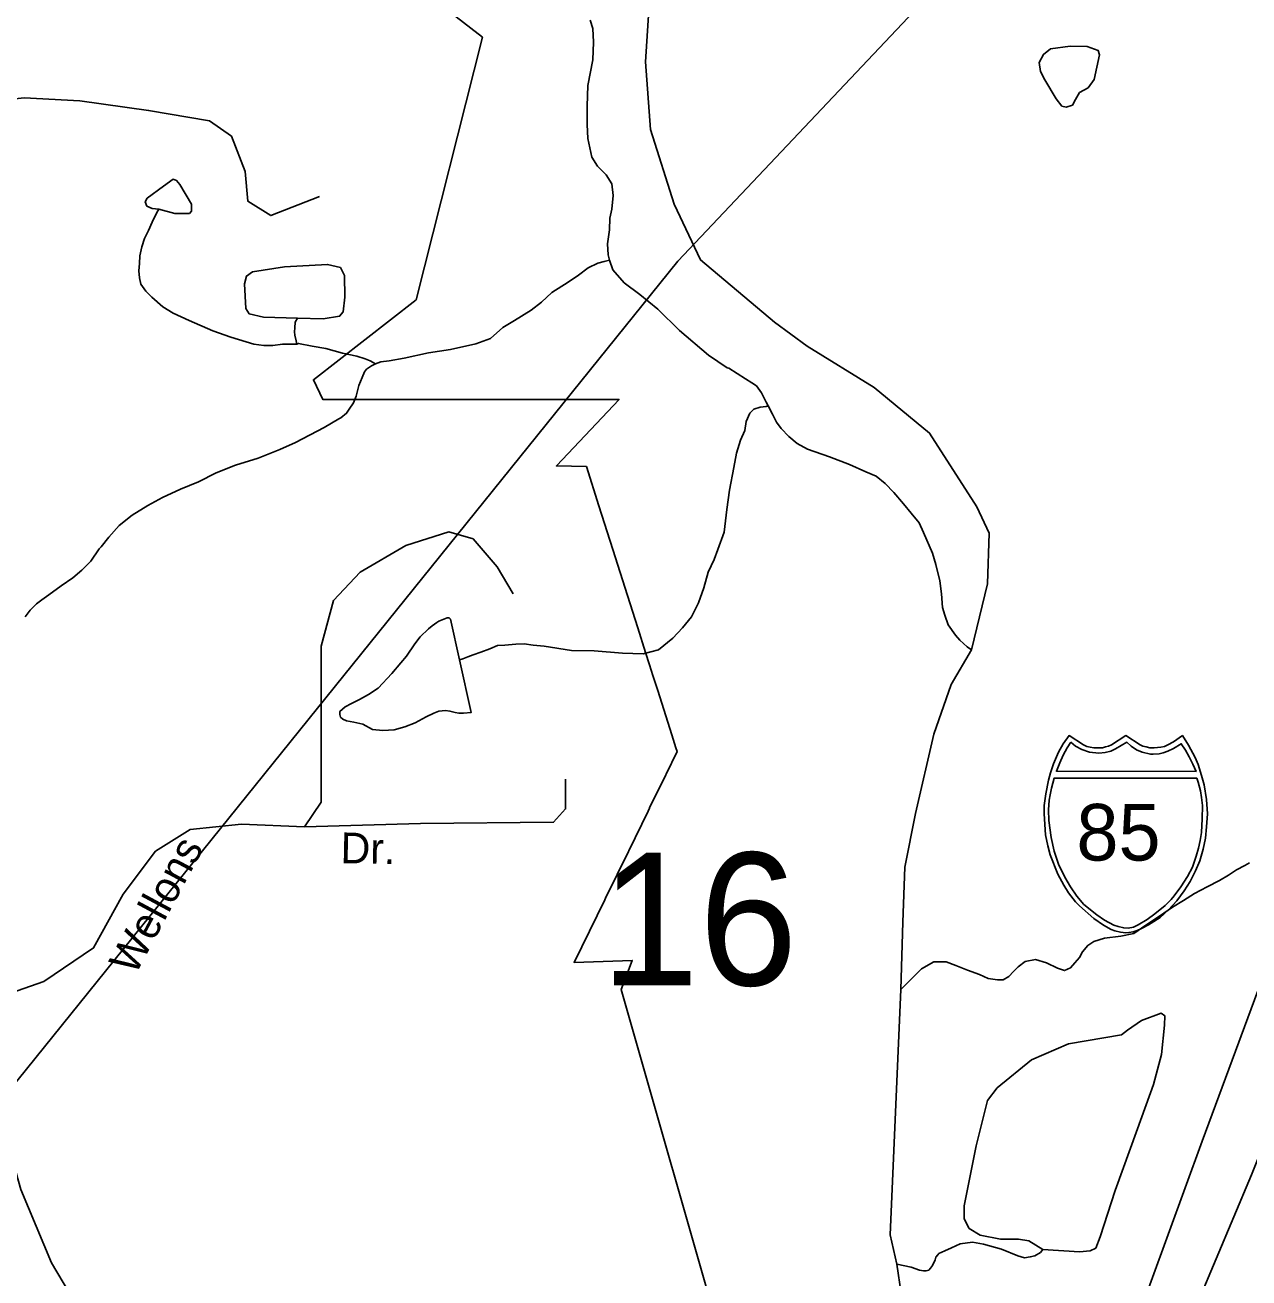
# Model space of a CAD drawing. Extents: x 2056842 to 2160602, y 826753 to 1016856.
# Drawn here: x 2066259 to 2070045, y 850316 to 854191 of the extents above; entities that cross this region are included whole.
import ezdxf

# ---------------------------------------------------------------- set-up
doc = ezdxf.new("R2010")
doc.units = 0
for name, color, linetype in [('Exist Boundary Political City Limit New', 7, 'Continuous'), ('Exist Hydrographic Creek Single Shore', 7, 'Continuous'), ('Exist Hydrographic Misc Water Feature', 7, 'Continuous'), ('Exist Road Non-System Type 51', 7, 'Continuous'), ('Exist Road Non-System Type 51 Label', 7, 'Continuous'), ('Exist Road Primary Interstate Divided Center Attributed', 7, 'Continuous'), ('Exist Road Primary Interstate Shield CELL', 7, 'Continuous'), ('Exist Road Primary Interstate Shield Number Label', 7, 'Continuous'), ('Exist Road Secondary Structure Standard Bridge Number Label', 7, 'Continuous'), ('Exist Road Secondary Type 51 Attributed', 7, 'Continuous'), ('Exist Utilities Gas Line', 7, 'Continuous'), ('Map Preparation Boundary City Limit Buffer Line', 7, 'Continuous')]:
    doc.layers.add(name, color=color, linetype=linetype)

msp = doc.modelspace()

# ---------------------------------------------------------------- linework, layer by layer
at = {"layer": 'Exist Boundary Political City Limit New'}
msp.add_lwpolyline([(2067132, 854572.3), (2067673.5, 854152.8), (2067469, 853340.9), (2067150.9, 853093.5), (2067179.6, 853032.6), (2067340.5, 853032.6), (2067723, 853032.6), (2068096.2, 853032.5), (2067902.6, 852827), (2067995.5, 852824.9), (2068034.2, 852703.3), (2068077.2, 852568.1), (2068122.2, 852426.6), (2068154.1, 852326.4), (2068178.5, 852250.1), (2068190.8, 852211.5), (2068201, 852179.3), (2068215.9, 852132.4), (2068259.5, 851995), (2068272.1, 851955.5), (2068275.9, 851943.8), (2068241.5, 851873.5), (2068240.8, 851871.8), (2068190.9, 851769.8), (2068190, 851768.1), (2068185.9, 851759.6), (2068126, 851636.9), (2068125, 851634.9), (2068054.1, 851489.8), (2068052.2, 851484.6), (2067957.1, 851291.3), (2068137, 851297.5), (2068103, 851207.4), (2068419.8, 850100.1)], dxfattribs=at)
at = {"layer": 'Exist Hydrographic Creek Single Shore'}
for points in [[(2069186.7, 852257.8), (2069236, 852462.5), (2069241.1, 852618.7), (2069202.7, 852700.6), (2069056.9, 852928.5), (2068885.6, 853069.9), (2068678.4, 853197.9), (2068577.3, 853272.1), (2068348.6, 853464.2), (2068266.7, 853637), (2068193.8, 853867.4), (2068178.4, 854076.7), (2068197.6, 854381.3)], [(2068007.3, 854205.4), (2068015.3, 854179.4), (2068017.1, 854137.3), (2068015.3, 854083.2), (2067999.5, 854003.3), (2067997.6, 853939.5), (2067997.8, 853883.4), (2067999.7, 853839.3), (2068011.8, 853781.5), (2068030, 853753.6), (2068055.9, 853727.3), (2068074.1, 853699.4), (2068078, 853663.5), (2068073.9, 853621.5), (2068068, 853593.6), (2068066.3, 853557.7), (2068060.2, 853513.7), (2068062.6, 853479.6), (2068066.3, 853463.6)], [(2067343.1, 853142.4), (2067359.1, 853148.5), (2067385.1, 853152.3), (2067431.1, 853160.3), (2067507.3, 853176.4), (2067574.8, 853186.8), (2067653.1, 853205), (2067698.7, 853220.7), (2067737.2, 853255.1), (2067773.1, 853277.2), (2067824.8, 853309.2), (2067856.8, 853333.1), (2067888.5, 853363.2), (2067938.6, 853395.3), (2067970.8, 853417.3), (2068000.7, 853439.5), (2068030.2, 853453.7), (2068050.3, 853459.6), (2068066.3, 853463.6)], [(2068066.3, 853463.6), (2068076.6, 853433.6), (2068112.5, 853393.8), (2068160.4, 853357.7), (2068216.6, 853311.8), (2068282.9, 853245.8), (2068372.7, 853170), (2068431.1, 853130.4), (2068435.6, 853128.9), (2068487.1, 853096.3), (2068507.2, 853084.3), (2068521.3, 853074.5), (2068537.1, 853052.6), (2068551.3, 853024.5), (2068557.2, 853012.6)], [(2066258.8, 852360.2), (2066275, 852380.5), (2066294.7, 852400.2), (2066310.9, 852412.4), (2066332.6, 852428.6), (2066370.3, 852456.5), (2066406.4, 852480.7), (2066434.5, 852504.8), (2066462.6, 852532.6), (2066488, 852570.9), (2066494.6, 852576.8), (2066518.4, 852606.9), (2066550.2, 852642.7), (2066589.9, 852674.8), (2066638.3, 852704.8), (2066684.1, 852729.1), (2066740.2, 852755.1), (2066795.8, 852777.5), (2066849.7, 852805.4), (2066909.8, 852829.6), (2066979.7, 852851.4), (2067047.4, 852877.6), (2067095.8, 852899.9), (2067183.8, 852945.8), (2067229.3, 852972.2), (2067235.4, 852976.1), (2067253.5, 852990), (2067261.5, 853002.2), (2067275, 853022), (2067283, 853042.3), (2067291.2, 853076), (2067301.3, 853100.1), (2067309.3, 853118.3), (2067315.4, 853126.3), (2067331, 853136.1), (2067343.1, 853142.4)], [(2068557.2, 853012.6), (2068571.2, 852986.6), (2068583.3, 852962.4), (2068597.4, 852942.4), (2068621.4, 852918.5), (2068647.6, 852896.7), (2068679.4, 852878.9), (2068747.3, 852854.8), (2068809.6, 852831.1), (2068859.5, 852808.9), (2068891.7, 852795.2), (2068919.7, 852773), (2068945.8, 852745.2), (2068975.9, 852709.3), (2068999.7, 852681.4), (2069024.1, 852651.3), (2069037.9, 852621.6), (2069066.2, 852557.7), (2069076, 852521.7), (2069088.1, 852471.6), (2069094, 852431.8), (2069096.5, 852389.6), (2069104.3, 852365.7), (2069114.1, 852335.7), (2069136.5, 852303.6), (2069150.4, 852287.7), (2069172.6, 852267.7), (2069186.7, 852257.8)], [(2068968.5, 850267.6), (2068955.1, 850358.8), (2068934.5, 850448.8), (2068967.9, 851207.4), (2068974.5, 851416), (2068980.2, 851585.7), (2069013.4, 851752.1), (2069069.7, 851997.9), (2069123.5, 852151.2), (2069186.7, 852257.8)], [(2070045.9, 851599.2), (2070031.7, 851591.2), (2070005.7, 851577.4), (2069981.7, 851561.5), (2069954, 851545.4), (2069915.9, 851525.2), (2069875.9, 851504.9), (2069842.1, 851482.9), (2069808, 851462.8), (2069767.8, 851434.9), (2069726, 851406.7), (2069688.3, 851380.8), (2069648.1, 851372.7), (2069598.3, 851366.9), (2069564.4, 851356.6), (2069546.2, 851344.3), (2069530.2, 851324.5), (2069520.3, 851306.5), (2069506.6, 851290.3), (2069492.5, 851274.6), (2069474.4, 851266.3), (2069452.5, 851274.1), (2069418.2, 851290.3), (2069384.6, 851300.3), (2069352.4, 851294.2), (2069330.3, 851278.1), (2069316.5, 851263.9), (2069302.4, 851248.2), (2069284.5, 851237.9), (2069266.7, 851237.8), (2069238.4, 851242.1), (2069210.7, 851254), (2069174.2, 851267.6), (2069138.3, 851281.6), (2069108.6, 851293.8), (2069070.3, 851293.6), (2069032.1, 851271.7), (2069014.3, 851253.8), (2068967.9, 851207.4)]]:
    msp.add_lwpolyline(points, dxfattribs=at)
at = {"layer": 'Exist Hydrographic Misc Water Feature'}
for points in [[(2069413.2, 854021.1), (2069448, 853962.8), (2069465.9, 853939.3), (2069479.4, 853937), (2069498.4, 853942.6), (2069508.5, 853960.6), (2069520.9, 853981.9), (2069547.8, 853996.5), (2069565.7, 854022.3), (2069582.5, 854098.5), (2069578, 854112), (2069544.4, 854124.3), (2069491.7, 854125.5), (2069431.2, 854116.5), (2069408.8, 854099.7), (2069395.3, 854075), (2069399.8, 854046.9), (2069413.2, 854021.1)], [(2066672.4, 853621.1), (2066652.3, 853622.9), (2066635.6, 853630.6), (2066630.5, 853643.4), (2066636.9, 853654.9), (2066686.8, 853692), (2066717.5, 853713.8), (2066727.7, 853709.9), (2066738, 853697.1), (2066773.8, 853637), (2066773.8, 853615.2), (2066767.4, 853607.5), (2066722.6, 853607.5), (2066672.4, 853621.1)], [(2066672.4, 853621.1), (2066666, 853611.1), (2066652.5, 853581.1), (2066640.6, 853554.9), (2066628.5, 853530.8), (2066620.3, 853504.8), (2066614.3, 853476.9), (2066612.9, 853452.8), (2066610.5, 853430.8), (2066612.9, 853409), (2066616.6, 853388.9), (2066632.6, 853367), (2066650.8, 853348.9), (2066684.9, 853318.9), (2066716.9, 853299.1), (2066766.9, 853277.3), (2066839.3, 853245.2), (2066895.1, 853225.4), (2066967, 853203.5), (2066997, 853199.8), (2067025.1, 853199.6), (2067055, 853203.9), (2067099.3, 853203.7)], [(2067101.1, 853283.8), (2066996.4, 853287.5), (2066951.6, 853297.7), (2066941.4, 853314.4), (2066937.5, 853389.9), (2066943.9, 853414.2), (2066961.9, 853427), (2067061.6, 853442.4), (2067194.7, 853450.1), (2067234.3, 853441.1), (2067247.1, 853415.5), (2067248.4, 853349), (2067243.3, 853304.1), (2067231.8, 853290.1), (2067180.6, 853282.4), (2067101.1, 853283.8)], [(2067101.1, 853283.8), (2067094.8, 853271.8), (2067093.1, 853253.8), (2067092.7, 853241.7), (2067093.3, 853231.8), (2067097, 853213.8), (2067099.3, 853203.7)], [(2067099.3, 853203.7), (2067105, 853205.7), (2067147.1, 853197.7), (2067189.1, 853190.1), (2067240.8, 853176.2), (2067285.1, 853166.2), (2067311.3, 853158.2), (2067326.9, 853152.2), (2067343.1, 853142.4)], [(2067602.9, 852227), (2067612.7, 852230.8), (2067628.7, 852236.9), (2067644.5, 852243), (2067668.9, 852251.1), (2067696.4, 852261), (2067720.6, 852271.2), (2067742.7, 852273.1), (2067776.6, 852275.3), (2067802.4, 852277), (2067830.7, 852273.2), (2067864.8, 852269.2), (2067948.8, 852255.7), (2068019, 852255.6), (2068106.9, 852247.9), (2068170.7, 852245.9), (2068218.7, 852258.2), (2068262.6, 852294.1), (2068292.5, 852326.1), (2068320.2, 852360), (2068342.5, 852404.1), (2068358.3, 852450.4), (2068372.1, 852498.2), (2068390.3, 852538.1), (2068402, 852568.3), (2068421.7, 852622.6), (2068429.9, 852692.3), (2068437.9, 852752.4), (2068451.6, 852822.1), (2068459.8, 852866.3), (2068471.5, 852906.3), (2068485.4, 852936.3), (2068489.3, 852964.5), (2068501.2, 852990.3), (2068513.5, 853002.6), (2068533.2, 853008.6), (2068551.5, 853010.7), (2068557.2, 853012.6)], [(2067602.9, 852227), (2067639.2, 852064.9), (2067615, 852062.9), (2067601.1, 852062.9), (2067589, 852064.8), (2067573.2, 852068.8), (2067559, 852070.9), (2067539.1, 852068.7), (2067523.1, 852062.6), (2067499.1, 852050.8), (2067465.1, 852032.4), (2067433.3, 852020.6), (2067400.9, 852010.5), (2067365.5, 852008.6), (2067333.3, 852012.2), (2067303.3, 852028.2), (2067275.4, 852034.4), (2067253.1, 852038.2), (2067241.4, 852044.1), (2067235, 852050.3), (2067233, 852058.3), (2067233, 852068), (2067249, 852082.2), (2067268.9, 852092.2), (2067293.1, 852104.4), (2067321.2, 852120.4), (2067350.9, 852140.2), (2067393.1, 852184.6), (2067420.8, 852218.5), (2067439.1, 852238.4), (2067464.9, 852276.7), (2067480.9, 852298.6), (2067506.5, 852322.7), (2067518.4, 852332.7), (2067532.4, 852342.8), (2067538.7, 852346.7), (2067548.6, 852350.9), (2067564.6, 852357), (2067570.5, 852356.9), (2067574.4, 852352.6), (2067602.9, 852227)], [(2069407, 850403.2), (2069363.4, 850430.4), (2069331.4, 850435.6), (2069276.4, 850435.6), (2069213.7, 850448.4), (2069179.2, 850468.8), (2069163.9, 850498.3), (2069163.9, 850539.2), (2069201, 850724.8), (2069235.5, 850864.4), (2069266.2, 850904.1), (2069372.4, 850989.8), (2069486.2, 851039.7), (2069650, 851067.9), (2069669.2, 851082), (2069712.7, 851111.4), (2069772.8, 851134.5), (2069784.3, 851126.8), (2069783, 851097.3), (2069774.1, 851006.5), (2069749.8, 850914.3), (2069699.9, 850777.3), (2069630.8, 850586), (2069584.7, 850442.6), (2069570.7, 850408), (2069554, 850399.1), (2069520.8, 850396.5), (2069407, 850403.2)], [(2069407, 850403.2), (2069399.8, 850394.4), (2069381.9, 850384.5), (2069368.2, 850380.5), (2069349.9, 850378.4), (2069329.6, 850384.3), (2069279, 850404.8), (2069224, 850420.2), (2069189.4, 850426.6), (2069151.1, 850421.5), (2069124.2, 850408.7), (2069104.1, 850399.8), (2069085.6, 850391.6), (2069082.1, 850387.7), (2069076, 850379.7), (2069074.4, 850371.9), (2069066.2, 850353.7), (2069059.8, 850345.7), (2069054.1, 850339.7), (2069046.1, 850337.6), (2069038.1, 850337.6), (2069026, 850339.5), (2069000.1, 850349.5), (2068955.1, 850358.8)]]:
    msp.add_lwpolyline(points, dxfattribs=at)
at = {"layer": 'Exist Road Non-System Type 51'}
for points in [[(2065020.3, 853541.1), (2065169, 853565.9), (2065219.3, 853592.5), (2065364.1, 853657.5), (2065503, 853690.1), (2065579.8, 853734.4), (2065718.7, 853870.5), (2065899, 853920.8), (2066094.1, 853947.4), (2066256.6, 853965.1), (2066428, 853956.2), (2066640.8, 853926.7), (2066829.9, 853894.1), (2066897.9, 853846.8), (2066939.3, 853737.4), (2066948.1, 853645.7), (2067019.1, 853601.4), (2067169.8, 853660.5)], [(2067123.1, 851710.4), (2067175.1, 851787.3), (2067175.1, 852269.5), (2067212.5, 852410.8), (2067295.5, 852498.1), (2067436.8, 852581.2), (2067569.7, 852622.8), (2067644.5, 852602), (2067719.2, 852514.7), (2067769.1, 852431.6)], [(2067123.1, 851710.4), (2067482.5, 851720.8), (2067893.7, 851724.9), (2067931.1, 851766.5), (2067931.1, 851857.9)], [(2066130.2, 851167.3), (2066317.3, 851232.3), (2066471, 851336.3), (2066562.4, 851502.5), (2066662.1, 851635.5), (2066770.1, 851702.1), (2066927.9, 851718.7), (2067123.1, 851710.4)]]:
    msp.add_lwpolyline(points, dxfattribs=at)
at = {"layer": 'Exist Road Primary Interstate Divided Center Attributed'}
for points in [[(2074216.7, 860970.1), (2074021.5, 860500.2), (2073815.4, 859976.4), (2073622, 859511.9), (2073427.7, 859049.2), (2073236.9, 858626.2), (2073074.9, 858266.1), (2072932.8, 857987.1), (2072657.5, 857398.4), (2072403.7, 856861.9), (2072139.2, 856303.8), (2071877.4, 855733.1), (2071579.6, 855101.2), (2071273.6, 854409.9), (2071085.6, 853904), (2070902.9, 853421.6), (2070686.1, 852841.9), (2070467.5, 852262.2), (2070294.7, 851822.9), (2070133.7, 851371), (2069899.7, 850739.1), (2069637, 850017.2), (2069432.9, 849467.8)], [(2069680.8, 849743), (2069779.1, 849984.8), (2070052.7, 850634.7), (2070292, 851232.4), (2070483.7, 851707.7), (2070694.2, 852193.8), (2070934.4, 852778.9), (2071174.7, 853363.9), (2071371.7, 853832), (2071631.7, 854462.1), (2071899.9, 855124.6), (2072109.5, 855623.3), (2072403.7, 856334.4), (2072634.1, 856897.9), (2072835.6, 857393), (2073048, 857895.2), (2073172.1, 858176.1), (2073332.3, 858582.9), (2073503.2, 859015), (2073695.8, 859472.3), (2073907.2, 860005.2), (2074093.5, 860476.8), (2074268.9, 860894.5)]]:
    msp.add_lwpolyline(points, dxfattribs=at)
at = {"layer": 'Exist Road Primary Interstate Shield CELL'}
for points in [[(2069663.9, 851382.8), (2069673.4, 851383.7), (2069686.1, 851386.2), (2069698.5, 851390.2), (2069712.6, 851396.5), (2069733.5, 851408), (2069750.2, 851417.8), (2069769.6, 851430.8), (2069795.7, 851454.5), (2069821.7, 851482), (2069844.7, 851513), (2069863, 851542), (2069879, 851575.2), (2069892.5, 851606.1), (2069903.1, 851641.4), (2069910.2, 851675.6), (2069913.8, 851711.3), (2069916.1, 851750.9), (2069913.5, 851795.4), (2069905.7, 851841), (2069898.4, 851869.4), (2069887.4, 851903.3), (2069878.4, 851925), (2069857.6, 851963.4), (2069838.8, 851993), (2069811.6, 851973.8), (2069793.8, 851964.4), (2069783, 851959.5), (2069771.8, 851957.4), (2069751.3, 851954.9), (2069738.5, 851955.4), (2069726.5, 851958.1), (2069716.4, 851960.3), (2069708.1, 851964.4), (2069663.9, 851993), (2069619.6, 851964.4), (2069610.4, 851960.1), (2069600.9, 851958.1), (2069591.7, 851955.6), (2069576.6, 851954.9), (2069565, 851955.2), (2069553.1, 851957.4), (2069543.7, 851959.3), (2069533.2, 851964.4), (2069488.1, 851993), (2069470.4, 851967.3), (2069455.9, 851941.9), (2069440.6, 851906), (2069431, 851878.1), (2069424.2, 851855.3), (2069415.9, 851813.3), (2069411.6, 851776.7), (2069410.8, 851750.9), (2069415.5, 851686.4), (2069422.6, 851652), (2069429.8, 851624.2), (2069453.7, 851564.2), (2069471.6, 851530.6), (2069487, 851506.4), (2069508.6, 851479.3), (2069520.3, 851466.3), (2069565.1, 851427.1), (2069595, 851406.7), (2069618.9, 851393.8), (2069630.2, 851389.5), (2069647.7, 851384.6)], [(2069493.5, 851972.3), (2069482.5, 851955.3), (2069469.8, 851932.5), (2069459.7, 851908.8), (2069449.3, 851882.7), (2069880.9, 851882.5), (2069870.8, 851904.9), (2069860.1, 851927.5), (2069848.8, 851948), (2069835.1, 851967.9), (2069810.9, 851952.7), (2069793.3, 851944.4), (2069779.1, 851939.5), (2069767.1, 851936.8), (2069748.5, 851935.3), (2069740.2, 851935.8), (2069714.3, 851941.7), (2069696.7, 851948.8), (2069680, 851960), (2069666.5, 851972.7), (2069632.3, 851952), (2069617.1, 851945.3), (2069599.7, 851940.9), (2069580.6, 851938.5), (2069551.2, 851941.7), (2069528.1, 851949.6), (2069508.2, 851960)], [(2069883.4, 851861.2), (2069888.1, 851849), (2069894.4, 851822), (2069897.8, 851801.1), (2069901.2, 851777.2), (2069900, 851736), (2069898, 851693.4), (2069894.1, 851668.2), (2069888.9, 851645.3), (2069881.7, 851619.8), (2069870.2, 851586), (2069854.3, 851557.4), (2069834.4, 851525.5), (2069812.9, 851497.7), (2069803.6, 851486.1), (2069785.9, 851467.4), (2069753.6, 851441.6), (2069730.1, 851424), (2069701.9, 851407.3), (2069687.6, 851401), (2069671, 851397.5), (2069657.3, 851398.5), (2069640.6, 851402.9), (2069627.2, 851406.5), (2069597.8, 851422.5), (2069573.9, 851438.4), (2069534.1, 851471), (2069512.7, 851496.1), (2069492.6, 851525.5), (2069474.8, 851555.6), (2069455.7, 851595.3), (2069442.2, 851635.2), (2069432.4, 851678.3), (2069425.8, 851730.9), (2069425.1, 851763), (2069427.1, 851793.8), (2069430, 851810), (2069433.9, 851830), (2069441.8, 851861)]]:
    msp.add_lwpolyline(points, close=True, dxfattribs=at)
at = {"layer": 'Exist Road Secondary Type 51 Attributed'}
msp.add_lwpolyline([(2066976.4, 849302.5), (2066827.4, 849529.6), (2066583.4, 849954.6), (2066340.4, 850362), (2066245.9, 850589.6), (2066191.9, 850780.8), (2066158.6, 851005.3), (2066128.5, 851176.7), (2066064.1, 851299.4), (2065906.3, 851503), (2065491.9, 851988.3), (2065329.9, 852210.7), (2065215.7, 852418.6), (2065151.3, 852589), (2065154.4, 852718.9), (2065131.6, 852966.2), (2065106.6, 853138.7), (2065035, 853464), (2064941.5, 853954.5), (2064909.3, 854202.9), (2064896.9, 854433.6), (2064911.4, 854770.3), (2064936.5, 855014.5)], dxfattribs=at)
at = {"layer": 'Exist Utilities Gas Line'}
msp.add_lwpolyline([(2063216.6, 847084.7), (2065392.1, 849881.8), (2068277.7, 853460.4), (2070574.6, 855889.8)], dxfattribs=at)
at = {"layer": 'Map Preparation Boundary City Limit Buffer Line'}
msp.add_lwpolyline([(2067132, 854572.3), (2067673.5, 854152.8), (2067469, 853340.9), (2067150.9, 853093.5), (2067179.6, 853032.6), (2067340.5, 853032.6), (2067723, 853032.6), (2068096.2, 853032.5), (2067902.6, 852827), (2067995.5, 852824.9), (2068034.2, 852703.3), (2068077.2, 852568.1), (2068122.2, 852426.6), (2068154.1, 852326.4), (2068178.5, 852250.1), (2068190.8, 852211.5), (2068201, 852179.3), (2068215.9, 852132.4), (2068259.5, 851995), (2068272.1, 851955.5), (2068275.9, 851943.8), (2068241.5, 851873.5), (2068240.8, 851871.8), (2068190.9, 851769.8), (2068190, 851768.1), (2068185.9, 851759.6), (2068126, 851636.9), (2068125, 851634.9), (2068054.1, 851489.8), (2068052.2, 851484.6), (2067957.1, 851291.3), (2068137, 851297.5), (2068103, 851207.4), (2068419.8, 850100.1)], dxfattribs=at)

# ---------------------------------------------------------------- texts
at = {"layer": 'Exist Road Non-System Type 51 Label'}
for s, rotation, p in [('Dr.', 358.8674, (2067234.2, 851598.7)), ('Wellons', 61.7365, (2066598.8, 851248.3))]:
    msp.add_text(s, height=95, rotation=rotation, dxfattribs=at).set_placement(p)
at = {"layer": 'Exist Road Primary Interstate Shield Number Label'}
msp.add_text('85', height=175, dxfattribs=at).set_placement((2069511, 851606.6))
at = {"layer": 'Exist Road Secondary Structure Standard Bridge Number Label'}
msp.add_text('16', height=410.1, dxfattribs=at).set_placement((2068038.5, 851220.7))

doc.saveas('drawing.dxf')
